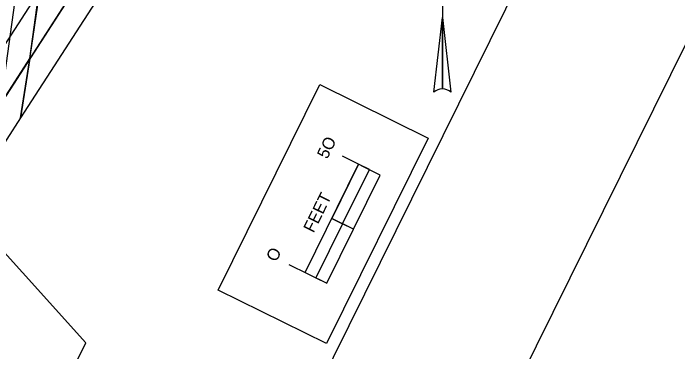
# Model space of a CAD drawing. Extents: x 14090526 to 14125274, y 8637242 to 8677144.
# Drawn here: x 14119507.4 to 14119782.5, y 8669266 to 8669406.2 of the extents above; entities that cross this region are included whole.
import ezdxf

# ---------------------------------------------------------------- set-up
doc = ezdxf.new("R2010")
doc.units = 0
for name, color, linetype in [('dsn_stg_shd_prev', 7, 'Continuous'), ('dsnCellsNorthArrow', 7, 'Continuous'), ('dsnCellsScaleBlock', 7, 'Continuous'), ('dsnNonPlotable', 7, 'Continuous'), ('dsnPaintExistingBrokenLaneLineWhite', 7, 'Continuous'), ('dsnPaintExistingEdgeLineRightWhite', 7, 'Continuous'), ('dsnPaintPlaceBrokenLineWhite', 7, 'Continuous'), ('dsnShadingPaved', 7, 'Continuous'), ('dsnStgShadingPropPav', 7, 'Continuous'), ('dsnTextOverlapEven', 7, 'Continuous')]:
    doc.layers.add(name, color=color, linetype=linetype)

msp = doc.modelspace()

# ---------------------------------------------------------------- linework, layer by layer
at = {"layer": 'dsn_stg_shd_prev'}
msp.add_lwpolyline([(14119545.92, 8669417.86), (14119510.41, 8669362.84), (14119514.62, 8669389.1), (14119518.63, 8669416.31)], dxfattribs=at)
at = {"layer": 'dsnCellsNorthArrow'}
for p, q in [((14119685.07, 8669448.08), (14119685.07, 8669374.84)), ((14119681.54, 8669373.43), (14119685.07, 8669404.42))]:
    msp.add_line(p, q, dxfattribs=at)
msp.add_lwpolyline([(14119685.07, 8669374.84), (14119685.07, 8669404.42), (14119688.59, 8669373.43)], dxfattribs=at)
for centre, radius, start, end in [((14119685.06, 8669369.74), 5.1, 89.9894, 133.619), ((14119685.07, 8669369.73), 5.11, 46.4021, 90.0006)]:
    msp.add_arc(centre, radius, start, end, dxfattribs=at)
at = {"layer": 'dsnCellsScaleBlock'}
msp.add_line((14119648.29, 8669316.75), (14119639.33, 8669321.18), dxfattribs=at)
msp.add_line((14119648.29, 8669316.75), (14119639.33, 8669321.18), dxfattribs=at)
for points in [[(14119592.28, 8669291.46), (14119634.39, 8669376.62), (14119679.21, 8669354.46), (14119637.1, 8669269.3)], [(14119637.1, 8669269.3), (14119592.28, 8669291.46), (14119634.39, 8669376.62), (14119679.21, 8669354.46)], [(14119643.78, 8669318.98), (14119654.86, 8669341.39), (14119650.41, 8669343.6), (14119639.33, 8669321.18)], [(14119637.21, 8669294.34), (14119648.29, 8669316.75), (14119643.78, 8669318.98), (14119632.7, 8669296.57)]]:
    msp.add_lwpolyline(points, close=True, dxfattribs=at)
for points in [[(14119621.53, 8669302.1), (14119637.21, 8669294.34), (14119659.37, 8669339.16), (14119643.69, 8669346.92)], [(14119628.25, 8669298.77), (14119650.41, 8669343.6)]]:
    msp.add_lwpolyline(points, dxfattribs=at)
at = {"layer": 'dsnNonPlotable'}
for points in [[(14119315.27, 8668607.09), (14120010, 8670012.23), (14119557.31, 8670236.05), (14118862.58, 8668830.91)], [(14119571.19, 8668959.34), (14119918.56, 8669661.91), (14120371.25, 8669438.09), (14120023.88, 8668735.52)]]:
    msp.add_lwpolyline(points, close=True, dxfattribs=at)
at = {"layer": 'dsnPaintExistingBrokenLaneLineWhite'}
msp.add_line((14119527.44, 8669429.79), (14119185.09, 8668899.43), dxfattribs=at)
at = {"layer": 'dsnPaintExistingEdgeLineRightWhite'}
msp.add_line((14119195.17, 8668892.92), (14119537.53, 8669423.29), dxfattribs=at)
at = {"layer": 'dsnPaintPlaceBrokenLineWhite'}
msp.add_arc((14156559.94, 8645459.12), 44137.45, 147.085241, 147.181675, dxfattribs=at)
at = {"layer": 'dsnShadingPaved'}
for points in [[(14119502.19, 8669368.54), (14119514.34, 8669387.38), (14119530.03, 8669501.55), (14119517.74, 8669481.68)], [(14119498.98, 8669345.14), (14119502.19, 8669368.54), (14119514.34, 8669387.38), (14119510.41, 8669362.84)]]:
    msp.add_lwpolyline(points, close=True, dxfattribs=at)
msp.add_lwpolyline([(14119537.53, 8669423.29), (14119537.53, 8669423.29), (14119195.17, 8668892.92)], dxfattribs=at)
at = {"layer": 'dsnStgShadingPropPav'}
msp.add_lwpolyline([(14119545.92, 8669417.86), (14119510.41, 8669362.84), (14119514.62, 8669389.1), (14119518.63, 8669416.31)], dxfattribs=at)
at = {"layer": 'dsnTextOverlapEven'}
msp.add_lwpolyline([(14119490.77, 8669175.11), (14119537.54, 8669269.69), (14119484.93, 8669327.85)], dxfattribs=at)

# ---------------------------------------------------------------- texts
at = {"layer": 'dsnCellsScaleBlock'}
for s, p in [('5O', (14119637.4, 8669345.48)), ('FEET', (14119631.76, 8669314.91)), ('O', (14119616.32, 8669302.85))]:
    msp.add_text(s, height=5, rotation=63.6912, dxfattribs=at).set_placement(p)

doc.saveas('drawing.dxf')
